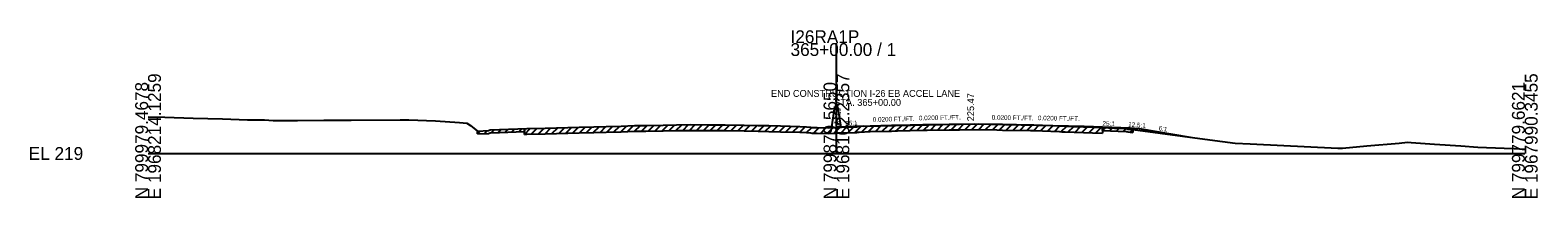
# Model space of a CAD drawing. Extents: x -26 to 304, y -10 to 7527.
# Drawn here: x -25.7 to 302.8, y 7490.3 to 7526.9 of the extents above; entities that cross this region are included whole.
import ezdxf

# ---------------------------------------------------------------- set-up
doc = ezdxf.new("R2010")
doc.units = 0
for name, color, linetype in [('RD_GPK_XS_Cell', 7, 'Continuous'), ('RD_XS_Base', 7, 'Continuous'), ('RD_XS_Box', 7, 'Continuous'), ('RD_XS_EarthShd', 7, 'Continuous'), ('RD_XS_EwShp', 7, 'Continuous'), ('RD_XS_ExGround', 7, 'Continuous'), ('RD_XS_ExPaveRet', 7, 'Continuous'), ('RD_XS_Misc_Line', 7, 'Continuous'), ('RD_XS_Pave', 7, 'Continuous'), ('RD_XS_PaveShd', 7, 'Continuous'), ('RD_XS_TX_Elev_EX', 7, 'Continuous'), ('RD_XS_TX_Elev_PR', 7, 'Continuous'), ('RD_XS_TX_Misc', 7, 'Continuous'), ('RD_XS_TX_MkPT', 7, 'Continuous'), ('RD_XS_TX_Profile', 7, 'Continuous'), ('RD_XS_TX_Station', 7, 'Continuous')]:
    doc.layers.add(name, color=color, linetype=linetype)

msp = doc.modelspace()

# ---------------------------------------------------------------- linework, layer by layer
at = {"layer": 'RD_GPK_XS_Cell'}
for p, q in [((150, 7500), (150, 7524.08)), ((0, 7500), (150, 7500)), ((150, 7500), (300, 7500))]:
    msp.add_line(p, q, dxfattribs=at)
at = {"layer": 'RD_XS_Base'}
for p, q in [((150, 7505.69), (150, 7505.75)), ((214, 7505.28), (214, 7505.59))]:
    msp.add_line(p, q, dxfattribs=at)
at = {"layer": 'RD_XS_Box'}
msp.add_line((216, 7505.43), (227.1, 7503.58), dxfattribs=at)
at = {"layer": 'RD_XS_EarthShd'}
for p, q in [((149, 7505.77), (149.67, 7510.25)), ((150, 7510.25), (149.67, 7510.25)), ((150, 7510.25), (150.33, 7510.25)), ((151, 7505.77), (150.33, 7510.25)), ((214, 7505.59), (216, 7505.43))]:
    msp.add_line(p, q, dxfattribs=at)
at = {"layer": 'RD_XS_ExGround'}
msp.add_lwpolyline([(0, 7508.03), (3.62, 7507.89), (9.86, 7507.72), (16.23, 7507.53), (21.65, 7507.37), (24.46, 7507.35), (25.38, 7507.31), (27.28, 7507.22), (32.57, 7507.21), (38.28, 7507.25), (44.27, 7507.25), (54.9, 7507.35), (55.95, 7507.36), (56.81, 7507.34), (62.63, 7507.15), (67.83, 7506.73), (69.46, 7506.6), (70.27, 7506.08), (71.79, 7504.89), (74.21, 7505.01), (74.54, 7505.16), (76.57, 7505.23), (82.56, 7505.44), (86.51, 7505.54), (93.97, 7505.74), (97.13, 7505.82), (99.81, 7505.89), (103.09, 7505.99), (106.02, 7506.09), (108.45, 7506.12), (112.27, 7506.18), (115.17, 7506.24), (118.28, 7506.3), (121.8, 7506.26), (123.7, 7506.25), (125.74, 7506.23), (129.9, 7506.19), (132.93, 7506.12), (135.24, 7506.07), (137.8, 7506), (142.05, 7505.9), (143.47, 7505.82), (144.32, 7505.77), (144.64, 7505.69), (145.8, 7505.66), (148.37, 7505.59), (150, 7505.69), (150.39, 7505.72), (151.09, 7505.75), (151.85, 7505.78), (154.38, 7505.82), (154.6, 7505.91), (154.95, 7505.93), (157.36, 7506.04), (162.01, 7506.15), (162.81, 7506.17), (163.31, 7506.19), (168.86, 7506.34), (169.76, 7506.35), (174.58, 7506.4), (176.84, 7506.43), (181.02, 7506.48), (184.94, 7506.39), (186.16, 7506.37), (192.28, 7506.28), (192.98, 7506.27), (198.58, 7506.04), (199.15, 7506.01), (199.81, 7505.99), (205.77, 7505.76), (207.97, 7505.65), (213.16, 7505.43), (213.47, 7505.32), (214.04, 7505.28), (214.61, 7505.24), (231.36, 7503.01), (236.91, 7502.26), (240.12, 7502.11), (259.29, 7501.16), (260.24, 7501.15), (265.56, 7501.64), (272.61, 7502.28), (274.46, 7502.44), (275.26, 7502.38), (280.34, 7502), (286.05, 7501.64), (289.79, 7501.41), (295.52, 7501.18), (297.7, 7501.09), (300, 7500.94)], dxfattribs=at)
at = {"layer": 'RD_XS_ExPaveRet'}
for p, q in [((71.79, 7504.27), (71.79, 7504.89)), ((71.79, 7504.27), (74.21, 7504.39)), ((74.21, 7504.39), (74.54, 7504.53)), ((74.54, 7504.53), (76.57, 7504.61)), ((76.57, 7504.61), (82, 7504.79)), ((82, 7504.17), (82, 7505.42)), ((82, 7505.42), (82, 7504.79)), ((82, 7504.17), (82.56, 7504.19)), ((82.56, 7504.19), (86.51, 7504.29)), ((86.51, 7504.29), (93.97, 7504.49)), ((93.97, 7504.49), (97.13, 7504.57)), ((97.13, 7504.57), (99.81, 7504.64)), ((99.81, 7504.64), (103.09, 7504.74)), ((103.09, 7504.74), (106.02, 7504.84)), ((106.02, 7504.84), (108.45, 7504.87)), ((108.45, 7504.87), (112.27, 7504.93)), ((112.27, 7504.93), (115.17, 7504.99)), ((115.17, 7504.99), (118.28, 7505.05)), ((118.28, 7505.05), (121.8, 7505.01)), ((121.8, 7505.01), (123.7, 7505)), ((123.7, 7505), (125.74, 7504.98)), ((125.74, 7504.98), (129.9, 7504.94)), ((129.9, 7504.94), (132.93, 7504.87)), ((132.93, 7504.87), (135.24, 7504.82)), ((135.24, 7504.82), (137.8, 7504.75)), ((137.8, 7504.75), (142.05, 7504.65)), ((142.05, 7504.65), (143.47, 7504.57)), ((143.47, 7504.57), (144.32, 7504.52)), ((144.32, 7504.52), (144.64, 7504.44)), ((144.64, 7504.44), (145.8, 7504.41)), ((145.8, 7504.41), (148.37, 7504.34)), ((148.37, 7504.34), (150, 7504.44)), ((150, 7504.44), (150.39, 7504.47)), ((150.39, 7504.47), (151.09, 7504.5)), ((151.09, 7504.5), (151.85, 7504.53)), ((151.85, 7504.53), (154.38, 7504.57)), ((154.38, 7504.57), (154.6, 7504.66)), ((154.6, 7504.66), (154.95, 7504.68)), ((154.95, 7504.68), (157.36, 7504.79)), ((157.36, 7504.79), (162.01, 7504.9)), ((162.01, 7504.9), (162.81, 7504.92)), ((162.81, 7504.92), (163.31, 7504.94)), ((163.31, 7504.94), (168.86, 7505.09)), ((168.86, 7505.09), (169.76, 7505.1)), ((169.76, 7505.1), (174.58, 7505.15)), ((174.58, 7505.15), (176.84, 7505.18)), ((176.84, 7505.18), (181.02, 7505.23)), ((181.02, 7505.23), (184.94, 7505.14)), ((184.94, 7505.14), (186.16, 7505.12)), ((186.16, 7505.12), (192.28, 7505.03)), ((192.28, 7505.03), (192.98, 7505.02)), ((192.98, 7505.02), (198.58, 7504.79)), ((198.58, 7504.79), (199.15, 7504.76)), ((199.15, 7504.76), (199.81, 7504.74)), ((199.81, 7504.74), (205.77, 7504.51)), ((205.77, 7504.51), (207.97, 7504.4)), ((207.97, 7504.4), (208, 7504.4)), ((208, 7505.65), (208, 7504.4)), ((208, 7505.02), (208, 7505.65)), ((208, 7505.02), (213.16, 7504.81)), ((213.16, 7504.81), (213.47, 7504.7)), ((213.47, 7504.7), (214.04, 7504.65)), ((214.04, 7504.65), (214.61, 7504.61)), ((214.61, 7505.24), (214.61, 7504.61))]:
    msp.add_line(p, q, dxfattribs=at)
at = {"layer": 'RD_XS_Misc_Line'}
for p, q in [((71.79, 7504.27), (72.45, 7504.93)), ((73.29, 7504.34), (73.95, 7505)), ((74.79, 7504.54), (75.44, 7505.19)), ((76.29, 7504.6), (76.94, 7505.25)), ((77.79, 7504.65), (78.44, 7505.3)), ((79.29, 7504.7), (79.94, 7505.35)), ((80.79, 7504.75), (81.44, 7505.4)), ((82, 7504.17), (83.29, 7505.46)), ((83.5, 7504.21), (84.78, 7505.49)), ((85, 7504.25), (86.28, 7505.53)), ((86.5, 7504.29), (87.78, 7505.57)), ((88, 7504.33), (89.28, 7505.61)), ((89.5, 7504.37), (90.78, 7505.65)), ((91, 7504.41), (92.28, 7505.69)), ((92.5, 7504.45), (93.78, 7505.73)), ((94, 7504.49), (95.28, 7505.77)), ((95.5, 7504.53), (96.78, 7505.81)), ((97, 7504.57), (98.28, 7505.85)), ((98.5, 7504.6), (99.78, 7505.88)), ((100, 7504.64), (101.29, 7505.93)), ((101.5, 7504.69), (102.79, 7505.98)), ((103, 7504.74), (104.29, 7506.03)), ((104.5, 7504.79), (105.79, 7506.09)), ((106, 7504.84), (107.27, 7506.11)), ((107.5, 7504.86), (108.77, 7506.13)), ((109, 7504.88), (110.27, 7506.15)), ((110.5, 7504.91), (111.77, 7506.18)), ((112, 7504.93), (113.27, 7506.2)), ((113.5, 7504.96), (114.77, 7506.23)), ((115, 7504.98), (116.28, 7506.26)), ((116.5, 7505.01), (117.78, 7506.29)), ((118, 7505.05), (119.25, 7506.29)), ((119.5, 7505.04), (120.74, 7506.28)), ((121, 7505.02), (122.24, 7506.26)), ((122.5, 7505.01), (123.74, 7506.25)), ((124, 7505), (125.24, 7506.24)), ((125.5, 7504.98), (126.74, 7506.22)), ((127, 7504.97), (128.24, 7506.21)), ((128.5, 7504.95), (129.74, 7506.19)), ((130, 7504.94), (131.22, 7506.16)), ((131.5, 7504.9), (132.72, 7506.13)), ((133, 7504.87), (134.22, 7506.09)), ((134.5, 7504.84), (135.72, 7506.06)), ((136, 7504.8), (137.22, 7506.02)), ((137.5, 7504.76), (138.72, 7505.98)), ((139, 7504.73), (140.22, 7505.95)), ((140.5, 7504.69), (141.72, 7505.91)), ((142, 7504.66), (143.18, 7505.84)), ((143.5, 7504.57), (144.62, 7505.69)), ((145, 7504.43), (146.22, 7505.65)), ((146.5, 7504.39), (147.72, 7505.61)), ((148, 7504.35), (149.3, 7505.65)), ((149.5, 7504.41), (150.83, 7505.74)), ((151, 7504.5), (152.29, 7505.78)), ((152.5, 7504.54), (153.77, 7505.81)), ((154, 7504.57), (155.38, 7505.95)), ((155.5, 7504.7), (156.81, 7506.02)), ((157, 7504.78), (158.29, 7506.07)), ((158.5, 7504.82), (159.78, 7506.1)), ((160, 7504.86), (161.28, 7506.14)), ((161.5, 7504.89), (162.78, 7506.17)), ((163, 7504.93), (164.29, 7506.21)), ((164.5, 7504.97), (165.79, 7506.25)), ((166, 7505.01), (167.29, 7506.29)), ((167.5, 7505.05), (168.79, 7506.34)), ((169, 7505.09), (170.26, 7506.35)), ((170.5, 7505.11), (171.76, 7506.37)), ((172, 7505.12), (173.26, 7506.39)), ((173.5, 7505.14), (174.76, 7506.4)), ((175, 7505.16), (176.26, 7506.42)), ((176.5, 7505.17), (177.77, 7506.44)), ((178, 7505.19), (179.27, 7506.46)), ((179.5, 7505.21), (180.77, 7506.48)), ((181, 7505.23), (182.22, 7506.45)), ((182.5, 7505.2), (183.72, 7506.42)), ((184, 7505.16), (185.22, 7506.38)), ((185.5, 7505.13), (186.73, 7506.36)), ((187, 7505.11), (188.23, 7506.34)), ((188.5, 7505.09), (189.73, 7506.32)), ((190, 7505.07), (191.23, 7506.3)), ((191.5, 7505.04), (192.73, 7506.28)), ((193, 7505.02), (194.2, 7506.22)), ((194.5, 7504.96), (195.7, 7506.16)), ((196, 7504.89), (197.2, 7506.09)), ((197.5, 7504.83), (198.7, 7506.03)), ((199, 7504.77), (200.2, 7505.97)), ((200.5, 7504.71), (201.7, 7505.92)), ((202, 7504.65), (203.2, 7505.86)), ((203.5, 7504.6), (204.7, 7505.8)), ((205, 7504.54), (206.2, 7505.74)), ((206.5, 7504.47), (207.69, 7505.66)), ((208, 7505.02), (208.6, 7505.62)), ((209.5, 7504.96), (210.1, 7505.56)), ((211, 7504.9), (211.6, 7505.5)), ((212.5, 7504.83), (213.1, 7505.43)), ((214, 7504.66), (214.58, 7505.24))]:
    msp.add_line(p, q, dxfattribs=at)
at = {"layer": 'RD_XS_Pave'}
for p, q in [((156, 7505.99), (180, 7506.47)), ((180, 7506.47), (204, 7505.99))]:
    msp.add_line(p, q, dxfattribs=at)
at = {"layer": 'RD_XS_PaveShd'}
for p, q in [((156, 7505.99), (150, 7505.75)), ((204, 7505.99), (214, 7505.59))]:
    msp.add_line(p, q, dxfattribs=at)
at = {"layer": 'RD_XS_TX_Elev_PR'}
for p, q in [((150, 7505.69), (150.39, 7505.72)), ((150.39, 7505.72), (151.09, 7505.75)), ((151.09, 7505.75), (151.85, 7505.78)), ((151.85, 7505.78), (154.38, 7505.82)), ((154.38, 7505.82), (154.6, 7505.91)), ((154.6, 7505.91), (154.95, 7505.93)), ((154.95, 7505.93), (157.36, 7506.04)), ((157.36, 7506.04), (162.01, 7506.15)), ((162.01, 7506.15), (162.81, 7506.17)), ((162.81, 7506.17), (163.31, 7506.19)), ((163.31, 7506.19), (168.86, 7506.34)), ((168.86, 7506.34), (169.76, 7506.35)), ((169.76, 7506.35), (174.58, 7506.4)), ((174.58, 7506.4), (176.84, 7506.43)), ((176.84, 7506.43), (181.02, 7506.48)), ((181.02, 7506.48), (184.94, 7506.39)), ((184.94, 7506.39), (186.16, 7506.37)), ((186.16, 7506.37), (192.28, 7506.28)), ((192.28, 7506.28), (192.98, 7506.27)), ((192.98, 7506.27), (198.58, 7506.04)), ((198.58, 7506.04), (199.15, 7506.01)), ((199.15, 7506.01), (199.81, 7505.99)), ((199.81, 7505.99), (205.77, 7505.76)), ((205.77, 7505.76), (207.97, 7505.65)), ((207.97, 7505.65), (208, 7505.65)), ((207.97, 7505.65), (210.56, 7505.54)), ((210.56, 7505.54), (213.16, 7505.43)), ((213.16, 7505.43), (213.47, 7505.32)), ((213.47, 7505.32), (214, 7505.28))]:
    msp.add_line(p, q, dxfattribs=at)

# ---------------------------------------------------------------- texts
at = {"layer": 'RD_GPK_XS_Cell'}
for s, p in [('I26RA1P', (140, 7524.08)), ('365+00.00 / 1', (140, 7521.28)), ('EL 219', (-26, 7498.6))]:
    msp.add_text(s, height=2.8, dxfattribs=at).set_placement(p)
for s, p in [('E 1968214.1259', (2.8, 7490)), ('E 1968102.2357', (152.8, 7490)), ('E 1967990.3455', (302.8, 7490)), ('N 799979.4678', (0, 7490)), ('N 799879.5650', (150, 7490)), ('N 799779.6621', (300, 7490))]:
    msp.add_text(s, height=2.8, rotation=90, dxfattribs=at).set_placement(p)
at = {"layer": 'RD_XS_EwShp'}
for s, p in [('END CONSTRUCTION I-26 EB ACCEL LANE', (135.73, 7512.36)), ('STA. 365+00.00', (149.52, 7510.39))]:
    msp.add_text(s, height=1.5, dxfattribs=at).set_placement(p)
at = {"layer": 'RD_XS_TX_Elev_EX'}
msp.add_text('224.69', height=1, rotation=90, dxfattribs=at).set_placement((151, 7505.69))
at = {"layer": 'RD_XS_TX_Misc'}
msp.add_text('12.5:1', height=1, rotation=355.4261, dxfattribs=at).set_placement((213.54, 7505.88))
at = {"layer": 'RD_XS_TX_MkPT'}
for rotation, p in [(2.2906, (151.94, 7506.08)), (357.7094, (207.96, 7506.08))]:
    msp.add_text('25:1', height=1, rotation=rotation, dxfattribs=at).set_placement(p)
at = {"layer": 'RD_XS_TX_Profile'}
for s, rotation, p in [('0.0200 FT./FT.', 1.1458, (157.92, 7506.92)), ('0.0200 FT./FT.', 1.1458, (167.98, 7507.23)), ('0.0200 FT./FT.', 358.8542, (183.83, 7507.39)), ('0.0200 FT./FT.', 358.8542, (193.89, 7507.27)), ('6:1', 350.5377, (220.15, 7505.07))]:
    msp.add_text(s, height=1, rotation=rotation, dxfattribs=at).set_placement(p)
at = {"layer": 'RD_XS_TX_Station'}
msp.add_text(' 225.47', height=1.5, rotation=90, dxfattribs=at).set_placement((180, 7506.47))

doc.saveas('drawing.dxf')
